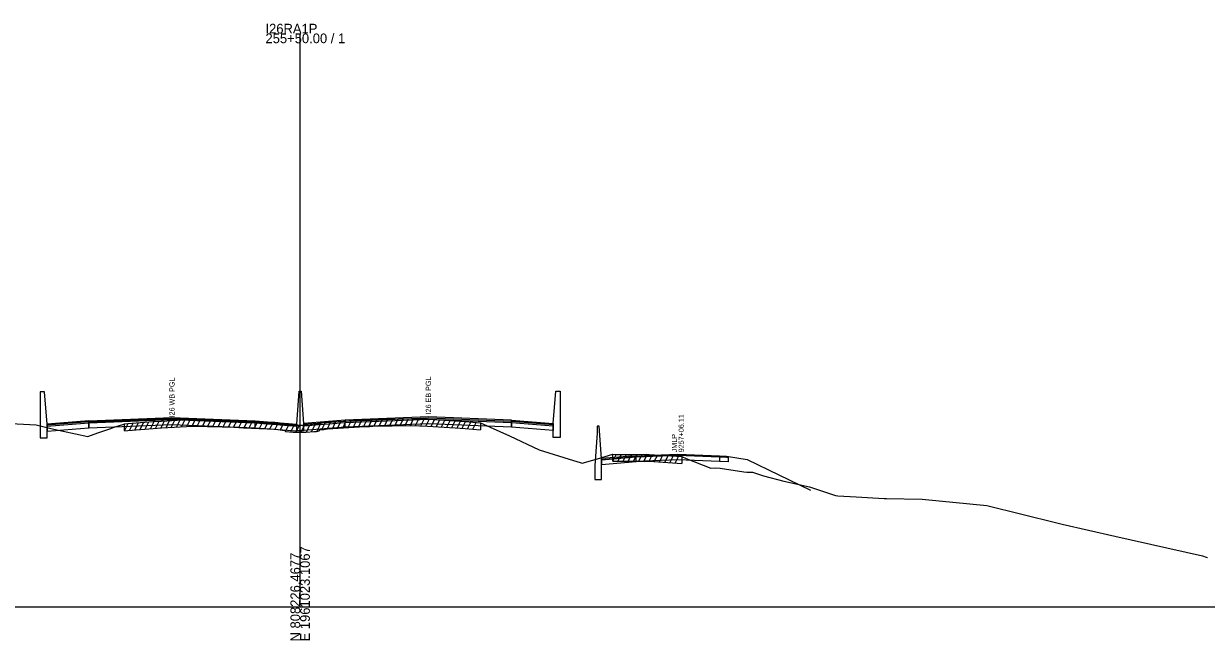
# Model space of a CAD drawing. Extents: x 1017 to 19997, y -1947 to 50737.
# Drawn here: x 10520.2 to 10861.5, y 5490.3 to 5668.4 of the extents above; entities that cross this region are included whole.
import ezdxf

# ---------------------------------------------------------------- set-up
doc = ezdxf.new("R2010")
doc.units = 0
for name, color, linetype in [('RD_GPK_XS_Cell', 7, 'Continuous'), ('RD_XS_Base', 7, 'Continuous'), ('RD_XS_ExGround', 7, 'Continuous'), ('RD_XS_ExPaveRet', 7, 'Continuous'), ('RD_XS_Greenside', 7, 'Continuous'), ('RD_XS_MedBWall', 7, 'Continuous'), ('RD_XS_Pave', 7, 'Continuous'), ('RD_XS_PaveOvlay', 7, 'Continuous'), ('RD_XS_TX_Notes', 7, 'Continuous')]:
    doc.layers.add(name, color=color, linetype=linetype)

msp = doc.modelspace()

# ---------------------------------------------------------------- linework, layer by layer
at = {"layer": 'RD_GPK_XS_Cell'}
for p, q in [((10600, 5500), (10600, 5665.54)), ((10000, 5500), (10600, 5500)), ((10600, 5500), (11200, 5500))]:
    msp.add_line(p, q, dxfattribs=at)
at = {"layer": 'RD_XS_Base'}
for points in [[(10539, 5553.04), (10527, 5552.08)], [(10527, 5552.08), (10527, 5550.74)], [(10527, 5550.74), (10539, 5551.7)], [(10539, 5551.7), (10539, 5553.04)], [(10539.05, 5551.7), (10539, 5551.7)], [(10539.05, 5553.04), (10539.05, 5551.7)], [(10539.05, 5551.7), (10563, 5552.67), (10587, 5551.7)], [(10587, 5551.7), (10587, 5553.04)], [(10599, 5552.1), (10587, 5553.04)], [(10587, 5551.7), (10599, 5550.76)], [(10599, 5550.76), (10599, 5552.1)], [(10601, 5550.91), (10601, 5552.25)], [(10613, 5551.85), (10601, 5550.91)], [(10613, 5551.85), (10613, 5553.19)], [(10660.95, 5551.85), (10637, 5552.81), (10613, 5551.85)], [(10660.95, 5551.85), (10660.95, 5553.19)], [(10661, 5551.85), (10660.95, 5551.85)], [(10661, 5553.19), (10661, 5551.85)], [(10661, 5553.18), (10673, 5552.22)], [(10661, 5551.84), (10661, 5553.18)], [(10673, 5550.88), (10661, 5551.84)], [(10673, 5552.22), (10673, 5550.88)], [(10697, 5543.26), (10687, 5542.46)], [(10697, 5543.26), (10709, 5543.74), (10721, 5543.26)], [(10697, 5541.93), (10697, 5543.26)], [(10721, 5543.26), (10721, 5541.95)], [(10721, 5543.26), (10723, 5543.18), (10723.5, 5543.16)], [(10723.5, 5543.16), (10723.5, 5541.83)], [(10687, 5542.46), (10687, 5541.13)], [(10687, 5541.13), (10697, 5541.93)], [(10721, 5541.95), (10709, 5542.41), (10697, 5541.93)], [(10723.5, 5541.83), (10721, 5541.95)]]:
    msp.add_lwpolyline(points, dxfattribs=at)
at = {"layer": 'RD_XS_ExGround'}
msp.add_lwpolyline([(10516.47, 5552.97), (10523.84, 5552.5), (10528.1, 5551.51), (10538.7, 5549.18), (10541.61, 5550.27), (10545.04, 5551.41), (10546.3, 5551.83), (10546.95, 5552.05), (10548.81, 5552.64), (10549.3, 5552.8), (10550.32, 5552.89), (10557.57, 5553.47), (10560, 5553.63), (10569.04, 5554.18), (10577.46, 5553.94), (10580.91, 5553.83), (10583.66, 5553.7), (10592.69, 5553.31), (10593.52, 5553.2), (10595.62, 5552.92), (10595.75, 5552.61), (10597.94, 5552.45), (10598.9, 5552.4), (10600, 5552.42), (10601.7, 5552.43), (10603.95, 5552.6), (10604.76, 5552.65), (10605.51, 5552.8), (10605.64, 5553.09), (10606.83, 5553.22), (10607.91, 5553.34), (10618.69, 5554.02), (10619.99, 5554.1), (10620.97, 5554.12), (10632.17, 5554.37), (10636.78, 5554.15), (10644.74, 5553.72), (10647.63, 5553.48), (10652.03, 5553.12), (10660.43, 5549.33), (10668.97, 5545.32), (10678.86, 5542.24), (10680.85, 5541.62), (10681.41, 5541.5), (10685.85, 5542.74), (10690.21, 5544.07), (10691.06, 5544.02), (10695.49, 5544.02), (10700, 5544.07), (10700.72, 5544.02), (10710.12, 5543.36), (10711.37, 5542.86), (10718.48, 5540.07), (10719.74, 5540.12), (10721.23, 5540.05), (10728.05, 5539), (10728.93, 5538.91), (10730.53, 5538.83), (10733.76, 5537.81), (10739.62, 5536.28), (10747, 5534.59), (10754.49, 5532.17), (10755.19, 5532.06), (10760.51, 5531.78), (10768.54, 5531.31), (10769.18, 5531.3), (10779.48, 5531.03), (10798.17, 5529.28), (10818.34, 5524.27), (10819.18, 5524.06), (10819.94, 5523.89), (10835.11, 5520.4), (10860.39, 5514.7), (10861.47, 5514.35), (10861.82, 5514.26)], dxfattribs=at)
at = {"layer": 'RD_XS_ExPaveRet'}
for p, q in [((10553.8, 5551.17), (10554.84, 5553.25)), ((10555.3, 5551.29), (10556.34, 5553.37)), ((10556.8, 5551.41), (10557.84, 5553.49)), ((10558.3, 5551.52), (10559.33, 5553.58)), ((10559.8, 5551.61), (10560.83, 5553.68)), ((10561.3, 5551.71), (10562.33, 5553.77)), ((10562.8, 5551.8), (10563.83, 5553.86)), ((10564.3, 5551.89), (10565.33, 5553.96)), ((10565.8, 5551.98), (10566.83, 5554.05)), ((10567.3, 5552.08), (10568.33, 5554.14)), ((10568.8, 5552.17), (10569.8, 5554.16)), ((10570.3, 5552.15), (10571.29, 5554.12)), ((10571.8, 5552.1), (10572.79, 5554.08)), ((10573.3, 5552.06), (10574.29, 5554.03)), ((10574.8, 5552.02), (10575.79, 5553.99)), ((10576.3, 5551.97), (10577.29, 5553.95)), ((10577.8, 5551.93), (10578.78, 5553.9)), ((10579.3, 5551.88), (10580.28, 5553.85)), ((10580.8, 5551.83), (10581.78, 5553.79)), ((10582.3, 5551.76), (10583.28, 5553.72)), ((10583.8, 5551.69), (10584.78, 5553.65)), ((10585.3, 5551.63), (10586.28, 5553.58)), ((10586.8, 5551.56), (10587.78, 5553.52)), ((10588.3, 5551.5), (10589.28, 5553.45)), ((10589.8, 5551.43), (10590.78, 5553.39)), ((10591.3, 5551.37), (10592.28, 5553.32)), ((10606.3, 5551.16), (10607.36, 5553.28)), ((10607.8, 5551.33), (10608.84, 5553.4)), ((10609.3, 5551.43), (10610.33, 5553.5)), ((10610.8, 5551.53), (10611.83, 5553.59)), ((10612.3, 5551.62), (10613.33, 5553.68)), ((10613.8, 5551.71), (10614.83, 5553.78)), ((10615.3, 5551.81), (10616.33, 5553.87)), ((10616.8, 5551.9), (10617.83, 5553.97)), ((10618.3, 5552), (10619.33, 5554.06)), ((10619.8, 5552.09), (10620.81, 5554.12)), ((10621.3, 5552.13), (10622.31, 5554.15)), ((10622.8, 5552.16), (10623.81, 5554.18)), ((10624.3, 5552.19), (10625.31, 5554.22)), ((10625.8, 5552.23), (10626.81, 5554.25)), ((10627.3, 5552.26), (10628.31, 5554.28)), ((10628.8, 5552.29), (10629.81, 5554.32)), ((10630.3, 5552.33), (10631.31, 5554.35)), ((10631.8, 5552.36), (10632.79, 5554.34)), ((10633.3, 5552.31), (10634.28, 5554.27)), ((10634.8, 5552.24), (10635.78, 5554.2)), ((10636.3, 5552.17), (10637.28, 5554.12)), ((10637.8, 5552.09), (10638.77, 5554.04)), ((10639.3, 5552.01), (10640.27, 5553.96)), ((10640.8, 5551.93), (10641.77, 5553.88)), ((10642.3, 5551.85), (10643.27, 5553.8)), ((10643.8, 5551.77), (10644.77, 5553.72)), ((10645.3, 5551.67), (10646.26, 5553.59)), ((10646.8, 5551.55), (10647.76, 5553.47)), ((10648.3, 5551.42), (10649.26, 5553.34)), ((10649.8, 5551.3), (10650.76, 5553.22)), ((10549.3, 5550.8), (10550.35, 5552.89)), ((10549.3, 5550.8), (10549.3, 5552.8)), ((10549.3, 5550.8), (10550.32, 5550.89)), ((10550.32, 5550.89), (10557.57, 5551.47)), ((10550.8, 5550.93), (10551.84, 5553.01)), ((10552.3, 5551.05), (10553.34, 5553.13)), ((10557.57, 5551.47), (10560, 5551.63)), ((10560, 5551.63), (10569.04, 5552.18)), ((10569.04, 5552.18), (10577.46, 5551.94)), ((10577.46, 5551.94), (10580.91, 5551.83)), ((10580.91, 5551.83), (10583.66, 5551.7)), ((10583.66, 5551.7), (10592.69, 5551.31)), ((10592.69, 5551.31), (10593.52, 5551.2)), ((10592.8, 5551.29), (10593.74, 5553.17)), ((10593.52, 5551.2), (10595.62, 5550.92)), ((10594.3, 5551.1), (10595.24, 5552.97)), ((10595.62, 5550.92), (10595.75, 5550.61)), ((10595.75, 5550.61), (10597.94, 5550.45)), ((10595.8, 5550.6), (10596.77, 5552.53)), ((10597.3, 5550.5), (10598.27, 5552.43)), ((10597.94, 5550.45), (10598.9, 5550.4)), ((10598.8, 5550.4), (10599.81, 5552.41)), ((10598.9, 5550.4), (10600, 5550.42)), ((10600, 5550.42), (10601.7, 5550.43)), ((10600.3, 5550.42), (10601.3, 5552.43)), ((10601.7, 5550.43), (10603.95, 5550.6)), ((10601.8, 5550.44), (10602.84, 5552.52)), ((10603.3, 5550.55), (10604.34, 5552.62)), ((10603.95, 5550.6), (10604.76, 5550.65)), ((10604.76, 5550.65), (10605.51, 5550.8)), ((10604.8, 5550.66), (10606.04, 5553.13)), ((10605.51, 5550.8), (10605.64, 5551.09)), ((10605.64, 5551.09), (10606.83, 5551.22)), ((10606.83, 5551.22), (10607.91, 5551.34)), ((10607.91, 5551.34), (10618.69, 5552.02)), ((10618.69, 5552.02), (10619.99, 5552.1)), ((10619.99, 5552.1), (10620.97, 5552.12)), ((10620.97, 5552.12), (10632.17, 5552.37)), ((10632.17, 5552.37), (10636.78, 5552.15)), ((10636.78, 5552.15), (10644.74, 5551.72)), ((10644.74, 5551.72), (10647.63, 5551.48)), ((10647.63, 5551.48), (10652.03, 5551.12)), ((10652.03, 5553.12), (10652.03, 5551.12)), ((10690.21, 5542.07), (10690.21, 5544.07)), ((10690.21, 5542.07), (10691.19, 5544.02)), ((10691.71, 5542.02), (10692.71, 5544.02)), ((10693.21, 5542.02), (10694.21, 5544.02)), ((10694.71, 5542.02), (10695.72, 5544.02)), ((10696.21, 5542.02), (10697.22, 5544.04)), ((10697.71, 5542.04), (10698.72, 5544.05)), ((10699.21, 5542.06), (10700.21, 5544.05)), ((10700.71, 5542.02), (10701.68, 5543.96)), ((10702.21, 5541.92), (10703.18, 5543.85)), ((10703.71, 5541.81), (10704.68, 5543.74)), ((10705.21, 5541.71), (10706.18, 5543.64)), ((10706.71, 5541.6), (10707.68, 5543.53)), ((10708.21, 5541.5), (10709.18, 5543.43)), ((10710.12, 5543.36), (10710.12, 5541.36)), ((10690.21, 5542.07), (10691.06, 5542.02)), ((10691.06, 5542.02), (10695.49, 5542.02)), ((10695.49, 5542.02), (10700, 5542.07)), ((10700, 5542.07), (10700.72, 5542.02)), ((10700.72, 5542.02), (10710.12, 5541.36))]:
    msp.add_line(p, q, dxfattribs=at)
at = {"layer": 'RD_XS_Greenside'}
for points in [[(10723, 5543.5), (10729, 5542.54)], [(10729, 5542.54), (10747.32, 5533.69)]]:
    msp.add_lwpolyline(points, dxfattribs=at)
at = {"layer": 'RD_XS_MedBWall'}
for points in [[(10527, 5552.76), (10526.25, 5562.1), (10525, 5562.1)], [(10525, 5562.1), (10525, 5548.76)], [(10599, 5552.76), (10599.75, 5562.24), (10600.25, 5562.24), (10601, 5552.9)], [(10673, 5552.9), (10673.75, 5562.24), (10675, 5562.24)], [(10675, 5562.24), (10675, 5548.9)], [(10527, 5548.76), (10527, 5552.76)], [(10599, 5550.76), (10599, 5552.76)], [(10601, 5550.76), (10599, 5550.76)], [(10601, 5552.9), (10601, 5550.76)], [(10673, 5548.9), (10673, 5552.9)], [(10685.75, 5550.12), (10685, 5540.78)], [(10687, 5542.78), (10686.25, 5552.12), (10685.75, 5552.12)], [(10685.75, 5552.12), (10685.75, 5550.12)], [(10525, 5548.76), (10527, 5548.76)], [(10675, 5548.9), (10673, 5548.9)], [(10685, 5540.78), (10685, 5536.78)], [(10687, 5536.78), (10687, 5542.78)], [(10685, 5536.78), (10687, 5536.78)]]:
    msp.add_lwpolyline(points, dxfattribs=at)
at = {"layer": 'RD_XS_Pave'}
for points in [[(10539, 5553.38), (10527, 5552.42)], [(10539, 5553.04), (10539, 5553.38)], [(10539.05, 5553.38), (10563, 5554.34), (10587, 5553.38)], [(10587, 5553.04), (10563, 5554.01), (10539.05, 5553.04)], [(10539.05, 5553.04), (10539.05, 5553.38)], [(10587, 5553.38), (10587, 5553.04)], [(10587, 5553.38), (10599, 5552.44)], [(10613, 5553.53), (10601, 5552.59)], [(10660.95, 5553.53), (10637, 5554.49), (10613, 5553.53)], [(10613, 5553.19), (10637, 5554.15), (10660.95, 5553.19)], [(10613, 5553.53), (10613, 5553.19)], [(10660.95, 5553.19), (10660.95, 5553.53)], [(10660.95, 5553.53), (10661, 5553.53)], [(10661, 5553.53), (10661, 5553.19)], [(10661, 5553.18), (10661, 5553.52)], [(10527, 5552.42), (10527, 5552.08)], [(10539.05, 5553.04), (10539, 5553.04)], [(10599, 5552.44), (10599, 5552.1)], [(10601, 5552.25), (10613, 5553.19)], [(10601, 5552.59), (10601, 5552.25)], [(10661, 5553.19), (10660.95, 5553.19)], [(10673, 5552.56), (10673, 5552.22)]]:
    msp.add_lwpolyline(points, dxfattribs=at)
at = {"layer": 'RD_XS_PaveOvlay'}
for points in [[(10539, 5553.72), (10527, 5552.76)], [(10539.05, 5553.72), (10539, 5553.72)], [(10539, 5553.72), (10539, 5553.38)], [(10539, 5553.38), (10539.05, 5553.38)], [(10539.05, 5553.72), (10563, 5554.68), (10587, 5553.72)], [(10539.05, 5553.38), (10539.05, 5553.72)], [(10587, 5553.72), (10587, 5553.38)], [(10587, 5553.72), (10599, 5552.76)], [(10613, 5553.86), (10601, 5552.9)], [(10660.95, 5553.86), (10637, 5554.82), (10613, 5553.86)], [(10613, 5553.86), (10613, 5553.53)], [(10660.95, 5553.53), (10660.95, 5553.86)], [(10660.95, 5553.86), (10661, 5553.86)], [(10661, 5553.86), (10661, 5553.53)], [(10661, 5553.86), (10673, 5552.9)], [(10661, 5553.52), (10661, 5553.86)], [(10673, 5552.56), (10661, 5553.52)], [(10527, 5552.76), (10527, 5552.42)], [(10599, 5552.76), (10599, 5552.44)], [(10601, 5552.9), (10601, 5552.59)], [(10673, 5552.9), (10673, 5552.56)], [(10697, 5543.58), (10687, 5542.78)], [(10687, 5542.46), (10697, 5543.26)], [(10697, 5543.58), (10709, 5544.06), (10721, 5543.58)], [(10721, 5543.26), (10709, 5543.74), (10697, 5543.26)], [(10697, 5543.26), (10697, 5543.58)], [(10721, 5543.58), (10721, 5543.26)], [(10721, 5543.58), (10723, 5543.5)], [(10723, 5543.18), (10721, 5543.26)], [(10723, 5543.5), (10723, 5543.18)], [(10687, 5542.78), (10687, 5542.46)]]:
    msp.add_lwpolyline(points, dxfattribs=at)

# ---------------------------------------------------------------- texts
at = {"layer": 'RD_GPK_XS_Cell'}
for s, p in [('I26RA1P', (10590, 5665.54)), ('255+50.00 / 1', (10590, 5662.74))]:
    msp.add_text(s, height=2.8, dxfattribs=at).set_placement(p)
for s, p in [('E 1961023.1067', (10602.8, 5490)), ('N 808226.4677', (10600, 5490))]:
    msp.add_text(s, height=2.8, rotation=90, dxfattribs=at).set_placement(p)
at = {"layer": 'RD_XS_TX_Notes'}
for s, p in [('I26 WB PGL', (10563.75, 5554.68)), ('I26 EB PGL', (10637.75, 5555.55)), (' 9257+06.11', (10710.73, 5544.03)), (' JMLP', (10708.77, 5544.03))]:
    msp.add_text(s, height=1.5, rotation=90, dxfattribs=at).set_placement(p)

doc.saveas('drawing.dxf')
